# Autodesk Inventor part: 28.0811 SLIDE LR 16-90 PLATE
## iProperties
Created: 2009-01
Part Number: 28.0811 SLIDE LR 16-90 PLATE
Document SubType Name: Modeling
Designer: Administrator
Density: 2.71 g/cm^3
Material: Aluminum-6061
Mass: 2449.91 g
Surface Area: 1170.67 cm^2
Volume: 904.025 cm^3
Author: Administrator
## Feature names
1. Base1
